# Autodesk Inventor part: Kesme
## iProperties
Shininess: 64.0
Length Units: 11269
Angle Units: 11279
Time Units: 11290
Mass Units: 11283
Length Display Precision: 3
Angle Display Precision: 2
Compacted: True
Part Number: Kesme
Document SubType Name: Sheet Metal
Created: 2003-09
Material: Stainless Steel, 440C
Designer: Ronald Myers
Manufacturer: Standard
Standards Organization: Custom
Density: 1 g/cm^3
Sheet Metal Rule: 0.8 mm Stainless
Density: 0.0
Volumn: 0.0
Area: 0.0
PropertySet Name: Model Information
Control State: 0
Master: False
Checked Out: False
Author: Ronald Myers
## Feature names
1. Plate1
2. Plate3
3. Bend2
4. Plate4
5. Bend3
6. Plate5
7. Bend4
8. Plate6
9. Bend5
